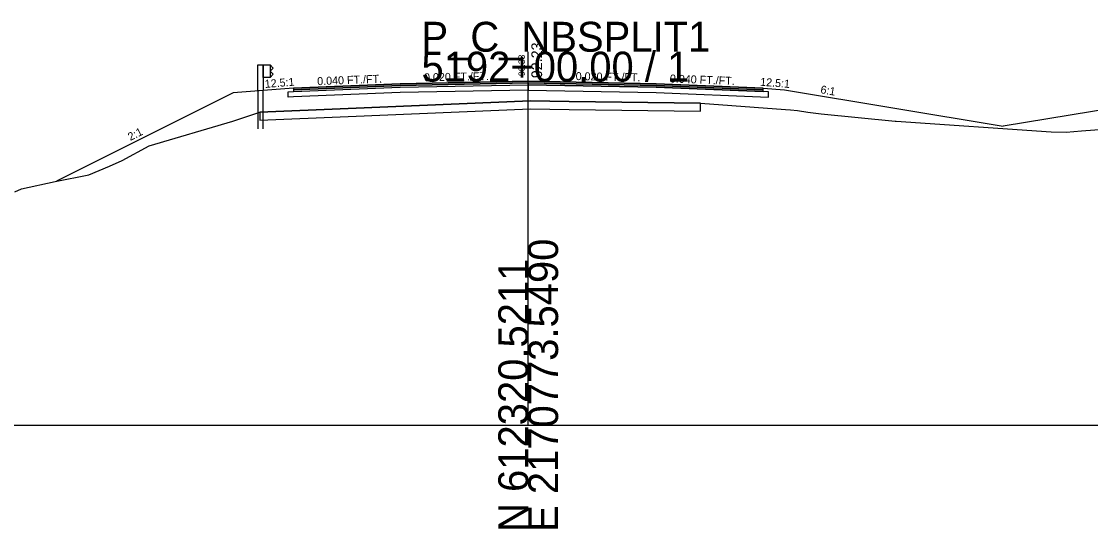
# Model space of a CAD drawing. Extents: x -26 to 1303, y -3010 to 12038.
# Drawn here: x 102.5 to 202.7, y 9490.3 to 9537.8 of the extents above; entities that cross this region are included whole.
import ezdxf

# ---------------------------------------------------------------- set-up
doc = ezdxf.new("R2010")
doc.units = 0
for name, color, linetype in [('RD_GPK_XS_Cell', 7, 'Continuous'), ('RD_PD_Final_TrvlWay', 7, 'Continuous'), ('RD_XS_Base', 7, 'Continuous'), ('RD_XS_ExGround', 7, 'Continuous'), ('RD_XS_ExPaveRet', 7, 'Continuous'), ('RD_XS_GR', 7, 'Continuous'), ('RD_XS_Greenside', 7, 'Continuous'), ('RD_XS_Pave', 7, 'Continuous'), ('RD_XS_PaveOvlay_CP', 7, 'Continuous'), ('RD_XS_TieSlope', 7, 'Continuous'), ('RD_XS_TX_Elev_EX', 7, 'Continuous'), ('RD_XS_TX_Elev_PR', 7, 'Continuous'), ('RD_XS_TX_ShdSlope', 7, 'Continuous'), ('RD_XS_TX_Slope', 7, 'Continuous')]:
    doc.layers.add(name, color=color, linetype=linetype)

msp = doc.modelspace()

# ---------------------------------------------------------------- linework, layer by layer
at = {"layer": 'RD_GPK_XS_Cell'}
for p, q in [((150, 9500), (150, 9535)), ((0, 9500), (150, 9500)), ((150, 9500), (300, 9500))]:
    msp.add_line(p, q, dxfattribs=at)
at = {"layer": 'RD_PD_Final_TrvlWay'}
for p, q in [((125.17, 9531.36), (124.67, 9531.32)), ((124.67, 9531.32), (124.67, 9527.76)), ((125.17, 9527.76), (125.17, 9531.36))]:
    msp.add_line(p, q, dxfattribs=at)
at = {"layer": 'RD_XS_Base'}
for p, q in [((150, 9531.91), (150, 9532.07)), ((150, 9532.07), (150, 9531.41)), ((127.5, 9531.25), (128, 9531.27)), ((127.5, 9530.75), (127.5, 9531.25)), ((127.5, 9531.25), (127.5, 9531.25)), ((128, 9531.27), (138, 9531.67)), ((128, 9531.27), (128, 9531.27)), ((138, 9531.17), (128, 9530.77)), ((138, 9531.67), (150, 9531.91)), ((138, 9531.67), (138, 9531.67)), ((150, 9531.41), (138, 9531.17)), ((138, 9531.17), (138, 9531.17)), ((150, 9531.91), (150, 9531.41)), ((162, 9531.67), (150, 9531.91)), ((150, 9531.91), (150, 9531.91)), ((150, 9531.41), (150, 9531.41)), ((150, 9531.41), (150, 9531.41)), ((150, 9531.41), (162, 9531.17)), ((172, 9531.27), (162, 9531.67)), ((162, 9531.17), (172.5, 9530.75)), ((164, 9531.59), (164, 9531.59)), ((164, 9531.09), (164, 9531.09)), ((172.5, 9531.25), (172, 9531.27)), ((172, 9531.27), (172, 9531.27)), ((172.5, 9530.75), (172.5, 9531.25)), ((172.5, 9531.25), (172.5, 9531.25)), ((128, 9530.77), (127.5, 9530.75)), ((127.5, 9530.75), (127.5, 9530.75)), ((127.5, 9530.75), (127.5, 9530.75)), ((128, 9530.77), (128, 9530.77)), ((172.5, 9530.75), (172.5, 9530.75)), ((172.5, 9530.75), (172.5, 9530.75))]:
    msp.add_line(p, q, dxfattribs=at)
at = {"layer": 'RD_XS_ExGround'}
msp.add_lwpolyline([(101.92, 9521.86), (102.55, 9522.16), (105.68, 9522.84), (108.85, 9523.47), (110.79, 9524.26), (111.95, 9524.8), (114.49, 9526.17), (122.32, 9528.5), (124.85, 9529.33), (133.15, 9529.67), (150.2, 9530.39), (153.85, 9530.34), (166.13, 9530.17), (174.09, 9529.57), (174.57, 9529.54), (175.23, 9529.49), (176.2, 9529.33), (177.44, 9529.19), (184.36, 9528.49), (184.46, 9528.49), (199, 9527.48), (200.38, 9527.45), (201.83, 9527.58), (212.32, 9528.37)], dxfattribs=at)
at = {"layer": 'RD_XS_ExPaveRet'}
msp.add_line((166.13, 9530.17), (153.85, 9530.34), dxfattribs=at)
for points in [[(153.85, 9530.34), (150.2, 9530.39), (150.2, 9530.39), (150.2, 9530.39), (133.15, 9529.67), (133.15, 9529.67), (124.85, 9529.33), (124.85, 9529.33), (124.85, 9528.58), (133.15, 9528.92), (133.15, 9528.92), (150.2, 9529.64), (150.2, 9529.64), (150.2, 9529.64), (153.85, 9529.59), (153.85, 9529.59), (166.13, 9529.42), (166.13, 9530.17), (166.13, 9530.17), (153.85, 9530.34), (153.85, 9530.34)], [(153.85, 9530.34), (150.2, 9530.39), (133.15, 9529.67), (124.85, 9529.33)], [(124.85, 9529.33), (124.85, 9528.58), (133.15, 9528.92), (150.2, 9529.64), (153.85, 9529.59), (166.13, 9529.42), (166.13, 9530.17)]]:
    msp.add_lwpolyline(points, dxfattribs=at)
at = {"layer": 'RD_XS_GR'}
for points in [[(125.17, 9533.76), (125.17, 9531.36), (124.67, 9531.32), (124.67, 9533.76), (124.92, 9533.76), (125.17, 9533.76)], [(125.83, 9533.76), (125.83, 9532.59), (125.17, 9532.59), (125.17, 9533.76), (125.83, 9533.76)], [(126.1, 9533.47), (125.83, 9533.76), (125.83, 9532.59), (125.83, 9532.59), (125.83, 9532.59), (126.1, 9532.88), (126.1, 9532.88), (125.83, 9533.17), (125.83, 9533.17), (126.1, 9533.47), (126.1, 9533.47)]]:
    msp.add_lwpolyline(points, dxfattribs=at)
at = {"layer": 'RD_XS_Greenside'}
for p, q in [((122.35, 9531.14), (105.81, 9522.87)), ((174, 9531.43), (194.49, 9528.01)), ((213.06, 9531.11), (194.49, 9528.01))]:
    msp.add_line(p, q, dxfattribs=at)
at = {"layer": 'RD_XS_Pave'}
for p, q in [((138, 9531.99), (128, 9531.59)), ((150, 9532.23), (138, 9531.99)), ((150, 9532.07), (138, 9531.83)), ((138, 9531.83), (150, 9532.07)), ((138, 9531.99), (138, 9531.99)), ((162, 9531.99), (150, 9532.23)), ((150, 9531.91), (150, 9532.07)), ((150, 9532.07), (162, 9531.83)), ((162, 9531.83), (150, 9532.07)), ((150, 9532.07), (150, 9531.91)), ((172, 9531.59), (162, 9531.99)), ((138, 9531.83), (128, 9531.43)), ((128, 9531.43), (138, 9531.83)), ((128, 9531.27), (138, 9531.67)), ((128, 9531.59), (128, 9531.59)), ((128, 9531.59), (128, 9531.43)), ((128, 9531.43), (128, 9531.43)), ((128, 9531.43), (128, 9531.27)), ((128, 9531.43), (128, 9531.43)), ((128, 9531.43), (128, 9531.43)), ((128, 9531.27), (128, 9531.27)), ((128, 9531.27), (128, 9531.27)), ((138, 9531.67), (150, 9531.91)), ((138, 9531.83), (138, 9531.83)), ((138, 9531.83), (138, 9531.83)), ((138, 9531.67), (138, 9531.67)), ((150, 9531.91), (150, 9531.91)), ((150, 9531.91), (150, 9531.91)), ((150, 9531.91), (162, 9531.67)), ((162, 9531.83), (172, 9531.43)), ((172, 9531.43), (162, 9531.83)), ((162, 9531.67), (172, 9531.27)), ((164, 9531.91), (164, 9531.91)), ((164, 9531.75), (164, 9531.75)), ((164, 9531.75), (164, 9531.75)), ((164, 9531.59), (164, 9531.59)), ((172, 9531.43), (172, 9531.59)), ((172, 9531.59), (172, 9531.59)), ((172, 9531.43), (172, 9531.43)), ((172, 9531.43), (172, 9531.43)), ((172, 9531.27), (172, 9531.43)), ((172, 9531.43), (172, 9531.43)), ((172, 9531.27), (172, 9531.27)), ((172, 9531.27), (172, 9531.27))]:
    msp.add_line(p, q, dxfattribs=at)
at = {"layer": 'RD_XS_PaveOvlay_CP'}
for p, q in [((128, 9531.59), (138, 9531.99)), ((138, 9531.99), (150, 9532.23)), ((150, 9532.23), (162, 9531.99)), ((162, 9531.99), (172, 9531.59))]:
    msp.add_line(p, q, dxfattribs=at)
at = {"layer": 'RD_XS_TieSlope'}
for p, q in [((128, 9531.59), (122.35, 9531.14)), ((172, 9531.59), (174, 9531.43))]:
    msp.add_line(p, q, dxfattribs=at)

# ---------------------------------------------------------------- texts
at = {"layer": 'RD_GPK_XS_Cell'}
for s, p in [('P_C_NBSPLIT1', (140, 9535)), ('5192+00.00 / 1', (140, 9532.2))]:
    msp.add_text(s, height=2.8, dxfattribs=at).set_placement(p)
for s, p in [('E 2170773.5490', (152.8, 9490)), ('N 612320.5211', (150, 9490))]:
    msp.add_text(s, height=2.8, rotation=90, dxfattribs=at).set_placement(p)
at = {"layer": 'RD_XS_TX_Elev_EX'}
msp.add_text('90.38', height=0.6, rotation=90, dxfattribs=at).set_placement((149.69, 9532.72))
at = {"layer": 'RD_XS_TX_Elev_PR'}
msp.add_text('92.23', height=1, rotation=90, dxfattribs=at).set_placement((151.3, 9532.52))
at = {"layer": 'RD_XS_TX_ShdSlope'}
for rotation, p in [(4.5739, (125.35, 9531.6)), (355.4261, (171.71, 9531.82))]:
    msp.add_text('12.5:1', height=0.75, rotation=rotation, dxfattribs=at).set_placement(p)
at = {"layer": 'RD_XS_TX_Slope'}
for s, rotation, p in [('0.020 FT./FT.', 1.1458, (140.25, 9532.22)), ('0.020 FT./FT.', 358.8542, (154.44, 9532.34)), ('0.040 FT./FT.', 2.2906, (130.25, 9531.86)), ('0.040 FT./FT.', 357.7094, (163.26, 9532.12)), ('6:1', 350.5377, (177.34, 9531.11)), ('2:1', 26.5651, (112.73, 9526.63))]:
    msp.add_text(s, height=0.75, rotation=rotation, dxfattribs=at).set_placement(p)

doc.saveas('drawing.dxf')
